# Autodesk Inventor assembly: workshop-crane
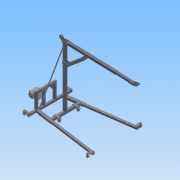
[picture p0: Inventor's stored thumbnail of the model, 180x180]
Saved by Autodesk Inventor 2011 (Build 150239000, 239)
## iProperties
Created: 2020-12
Part Number: workshop-crane
Document SubType Name: Assembly
Designer: PC
Author: PC
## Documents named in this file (7)
- C:\Users\PC\Documents\Inventor\workshop-crane-powered-by-drill\workshop-crane.iam
- C:\Users\PC\Documents\Inventor\workshop-crane-powered-by-drill\main-frame.iam
- C:\Users\PC\Documents\Inventor\workshop-crane-powered-by-drill\pivot-arm.iam
- C:\Users\PC\Documents\Inventor\workshop-crane-powered-by-drill\telescopic-tube.iam
- C:\Users\PC\Documents\Inventor\workshop-crane-powered-by-drill\left-leg.iam
- C:\Users\PC\Documents\Inventor\workshop-crane-powered-by-drill\right-leg.iam
- C:\Users\PC\Documents\Inventor\workshop-crane-powered-by-drill\arm.iam
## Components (6 placed, 6 different names)
1. main-frame:1 [sub-assembly] — Insert:1, Insert:2, Insert:3, Insert:4, Insert:5, Insert:6
2. pivot-arm:1 [sub-assembly] — Insert:1, Insert:7
3. telescopic-tube:1 [sub-assembly] — Insert:8, Angle:1
4. left-leg:1 [sub-assembly] — Insert:2, Insert:3
5. right-leg:1 [sub-assembly] — Insert:4, Insert:5
6. arm:1 [sub-assembly] — Insert:6, Insert:7, Insert:8, Angle:1
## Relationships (9: Insert 8, Angle 1)
- Insert:1: main-frame:1 ↔ pivot-arm:1
- Insert:2: main-frame:1 ↔ left-leg:1
- Insert:3: main-frame:1 ↔ left-leg:1
- Insert:4: main-frame:1 ↔ right-leg:1
- Insert:5: main-frame:1 ↔ right-leg:1
- Insert:6: main-frame:1 ↔ arm:1
- Insert:7: pivot-arm:1 ↔ arm:1
- Insert:8: telescopic-tube:1 ↔ arm:1
- Angle:1: telescopic-tube:1 ↔ arm:1
